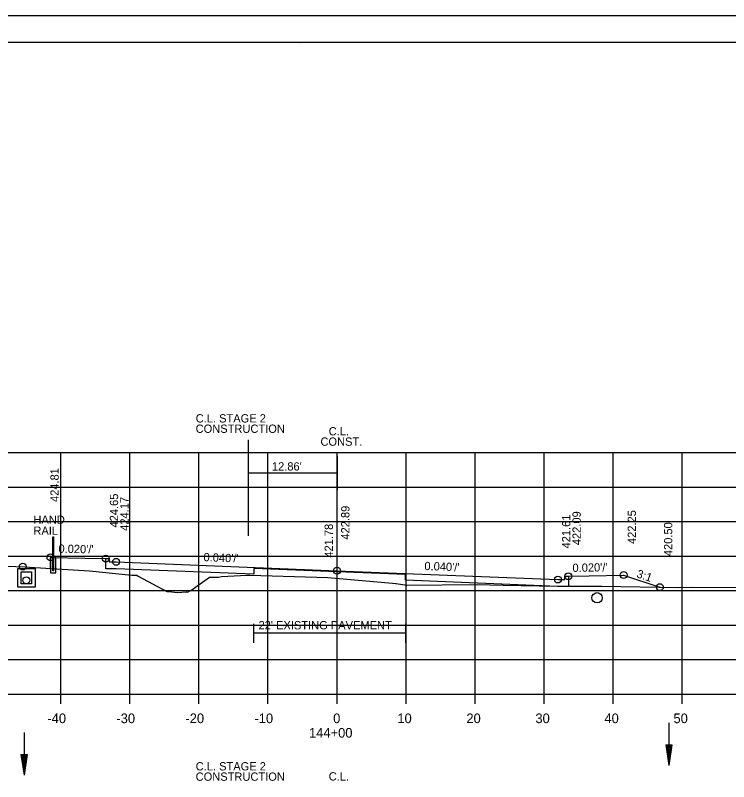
# Model space of a CAD drawing. Extents: x 1538688 to 1540766, y 656250 to 671912.
# Drawn here: x 1538811.6 to 1538914.9, y 663053.7 to 663164.7 of the extents above; entities that cross this region are included whole.
import ezdxf

# ---------------------------------------------------------------- set-up
doc = ezdxf.new("R2010")
doc.units = 0
for name, color, linetype in [('15', 7, 'Continuous'), ('18', 7, 'Continuous'), ('20', 7, 'Continuous'), ('22', 7, 'Continuous'), ('26', 7, 'Continuous'), ('39', 7, 'Continuous'), ('41', 7, 'Continuous'), ('42', 7, 'Continuous'), ('7', 7, 'Continuous'), ('Borings', 7, 'Continuous'), ('Default', 7, 'Continuous'), ('Horizontal Alignment', 7, 'Continuous'), ('RipRap', 7, 'Continuous'), ('Wall Heights', 7, 'Continuous')]:
    doc.layers.add(name, color=color, linetype=linetype)

msp = doc.modelspace()

# ---------------------------------------------------------------- linework, layer by layer
at = {"layer": '15'}
for p, q in [((1538905.79, 663059.03), (1538906.24, 663056.03)), ((1538905.79, 663059.03), (1538906.69, 663059.03)), ((1538905.87, 663059.03), (1538906.24, 663056.53)), ((1538905.95, 663059.03), (1538906.24, 663057.05)), ((1538906.02, 663059.03), (1538906.24, 663057.55)), ((1538906.1, 663059.03), (1538906.24, 663058.06)), ((1538906.17, 663059.03), (1538906.24, 663058.56)), ((1538906.69, 663059.03), (1538906.24, 663056.03)), ((1538906.39, 663059.03), (1538906.24, 663058.06)), ((1538906.54, 663059.03), (1538906.24, 663057.05)), ((1538906.62, 663059.03), (1538906.24, 663056.53)), ((1538906.47, 663059.03), (1538906.24, 663057.55)), ((1538906.31, 663059.03), (1538906.24, 663058.56)), ((1538812.39, 663057.6), (1538812.84, 663054.6)), ((1538812.39, 663057.6), (1538813.29, 663057.6)), ((1538812.47, 663057.6), (1538812.84, 663055.1)), ((1538812.54, 663057.6), (1538812.84, 663055.62)), ((1538812.62, 663057.6), (1538812.84, 663056.12)), ((1538812.7, 663057.6), (1538812.84, 663056.63)), ((1538812.77, 663057.6), (1538812.84, 663057.13)), ((1538813.29, 663057.6), (1538812.84, 663054.6)), ((1538812.99, 663057.6), (1538812.84, 663056.63)), ((1538813.14, 663057.6), (1538812.84, 663055.62)), ((1538813.22, 663057.6), (1538812.84, 663055.1)), ((1538813.06, 663057.6), (1538812.84, 663056.12)), ((1538812.91, 663057.6), (1538812.84, 663057.13))]:
    msp.add_line(p, q, dxfattribs=at)
at = {"layer": '18'}
msp.add_lwpolyline([(1538800.87, 663085.26), (1538813.02, 663084.82), (1538813.65, 663084.78), (1538822.3, 663084.24), (1538828.47, 663083.62), (1538829.18, 663083.58), (1538829.37, 663083.45), (1538833.55, 663081.21), (1538833.81, 663081.22), (1538835.09, 663081.07), (1538836.39, 663081.18), (1538836.52, 663081.15), (1538837.01, 663081.4), (1538839.7, 663083.31), (1538841, 663083.33), (1538841.44, 663083.4), (1538845.13, 663083.62), (1538845.36, 663083.62), (1538845.54, 663083.61), (1538856.87, 663083.25), (1538866.2, 663082.42), (1538866.65, 663082.38), (1538866.75, 663082.38), (1538868.3, 663082.17), (1538878.48, 663082.24), (1538882.26, 663082.13), (1538890.1, 663082.03), (1538896.52, 663082.02), (1538907.59, 663081.81), (1538909.58, 663081.85), (1538916.48, 663081.83)], dxfattribs=at)
at = {"layer": '20'}
msp.add_lwpolyline([(1538816.67, 663084.59), (1538816.67, 663086.17), (1538821.67, 663086.07), (1538824.67, 663086.01), (1538825.17, 663086.01), (1538825.18, 663085.51), (1538826.18, 663085.53), (1538858.18, 663084.25), (1538890.18, 663082.97), (1538891.18, 663082.95), (1538891.19, 663083.45), (1538891.69, 663083.45), (1538894.69, 663083.51), (1538899.69, 663083.61), (1538904.95, 663081.86)], dxfattribs=at)
at = {"layer": '22'}
for p, q in [((1538718.18, 663101.36), (1538998.18, 663101.36)), ((1538818.18, 663066.36), (1538818.18, 663101.36)), ((1538828.18, 663066.36), (1538828.18, 663101.36)), ((1538838.18, 663066.36), (1538838.18, 663101.36)), ((1538848.18, 663066.36), (1538848.18, 663101.36)), ((1538858.18, 663066.36), (1538858.18, 663101.36)), ((1538868.18, 663066.36), (1538868.18, 663101.36)), ((1538878.18, 663066.36), (1538878.18, 663101.36)), ((1538888.18, 663066.36), (1538888.18, 663101.36)), ((1538898.18, 663066.36), (1538898.18, 663101.36)), ((1538908.18, 663066.36), (1538908.18, 663101.36)), ((1538718.18, 663096.36), (1538998.18, 663096.36)), ((1538718.18, 663091.36), (1538998.18, 663091.36)), ((1538718.18, 663086.36), (1538998.18, 663086.36)), ((1538718.18, 663081.36), (1538998.18, 663081.36)), ((1538718.18, 663076.36), (1538998.18, 663076.36)), ((1538718.18, 663071.36), (1538998.18, 663071.36)), ((1538718.18, 663066.36), (1538998.18, 663066.36))]:
    msp.add_line(p, q, dxfattribs=at)
at = {"layer": '26'}
msp.add_line((1538687.78, 663164.71), (1539021.11, 663164.71), dxfattribs=at)
msp.add_lwpolyline([(1538687.77, 663164.71), (1539021.11, 663164.71), (1539021.11, 662951.38), (1538687.77, 662951.38)], close=True, dxfattribs=at)
for centre in [(1538816.67, 663086.17), (1538824.67, 663086.01), (1538812.66, 663084.84), (1538826.18, 663085.53), (1538858.18, 663084.25), (1538890.18, 663082.97), (1538891.69, 663083.45), (1538899.69, 663083.61), (1538904.95, 663081.86)]:
    msp.add_circle(centre, 0.5, dxfattribs=at)
at = {"layer": '39'}
for p, q in [((1538906.24, 663062.22), (1538906.24, 663056.03)), ((1538812.84, 663060.79), (1538812.84, 663054.6))]:
    msp.add_line(p, q, dxfattribs=at)
for points in [[(1538813.18, 663084.56), (1538814.43, 663084.56), (1538814.43, 663081.86), (1538813.18, 663081.86), (1538811.93, 663081.86), (1538811.93, 663084.56)], [(1538813.18, 663084.06), (1538813.93, 663084.06), (1538813.93, 663082.36), (1538813.18, 663082.36), (1538812.43, 663082.36), (1538812.43, 663084.06)]]:
    msp.add_lwpolyline(points, close=True, dxfattribs=at)
for centre, radius in [((1538813.18, 663082.86), 0.5), ((1538895.85, 663080.32), 0.75)]:
    msp.add_circle(centre, radius, dxfattribs=at)
at = {"layer": '41'}
for points in [[(1538817.13, 663089.17), (1538817.13, 663084.25), (1538817, 663084.25), (1538817, 663089.17), (1538817.13, 663089.17)], [(1538817, 663086.17), (1538816.67, 663086.17), (1538816.67, 663083.92), (1538817.46, 663083.92), (1538817.46, 663086.17), (1538817.13, 663086.17)]]:
    msp.add_lwpolyline(points, dxfattribs=at)
at = {"layer": '7'}
for p, q in [((1538846.1, 663076.56), (1538846.1, 663073.81)), ((1538868.1, 663076.56), (1538868.1, 663073.81)), ((1538868.1, 663075.19), (1538846.1, 663075.19))]:
    msp.add_line(p, q, dxfattribs=at)
at = {"layer": 'Borings'}
for p, q in [((1538718.18, 663066.36), (1538998.18, 663066.36)), ((1538818.18, 663064.96), (1538818.18, 663066.36)), ((1538828.18, 663064.96), (1538828.18, 663066.36)), ((1538838.18, 663064.96), (1538838.18, 663066.36)), ((1538848.18, 663064.96), (1538848.18, 663066.36)), ((1538858.18, 663064.96), (1538858.18, 663066.36)), ((1538868.18, 663064.96), (1538868.18, 663066.36)), ((1538878.18, 663064.96), (1538878.18, 663066.36)), ((1538888.18, 663064.96), (1538888.18, 663066.36)), ((1538898.18, 663064.96), (1538898.18, 663066.36)), ((1538908.18, 663064.96), (1538908.18, 663066.36))]:
    msp.add_line(p, q, dxfattribs=at)
at = {"layer": 'Default'}
for p, q in [((1538845.32, 663103.2), (1538845.32, 663089.29)), ((1538858.18, 663100.9), (1538858.18, 663095.9)), ((1538858.18, 663098.4), (1538845.32, 663098.4))]:
    msp.add_line(p, q, dxfattribs=at)
at = {"layer": 'RipRap'}
for p, q in [((1538700.18, 663160.82), (1539016.36, 663160.82)), ((1538852.7, 663160.56), (1538852.7, 663160.56)), ((1538852.7, 663160.56), (1538852.7, 663160.56))]:
    msp.add_line(p, q, dxfattribs=at)
at = {"layer": 'Wall Heights'}
msp.add_lwpolyline([(1538891.69, 663083.45), (1538891.69, 663081.95), (1538890.18, 663081.97), (1538868.11, 663082.86), (1538868.11, 663083.69), (1538858.18, 663084.09), (1538846.11, 663084.57), (1538846.11, 663083.74), (1538826.18, 663084.53), (1538824.67, 663084.51), (1538824.67, 663086.01)], dxfattribs=at)

# ---------------------------------------------------------------- texts
at = {"layer": '41'}
for s, p in [('424.81', (1538817.86, 663094.2)), ('424.65', (1538826.47, 663090.51)), ('424.17', (1538827.98, 663090.03)), ('422.89', (1538859.98, 663088.75)), ('421.61', (1538891.98, 663087.47)), ('422.09', (1538893.49, 663087.95)), ('422.25', (1538901.49, 663088.11)), ('421.78', (1538857.58, 663086.14)), ('420.50', (1538906.75, 663086.36))]:
    msp.add_text(s, height=1.2, rotation=90, dxfattribs=at).set_placement(p)
for s, p in [('HAND', (1538814.2, 663091.04)), ('RAIL', (1538814.2, 663089.45))]:
    msp.add_text(s, height=1.2, dxfattribs=at).set_placement(p)
at = {"layer": '42'}
for s, rotation, p in [("0.020'/'", 358.8542, (1538817.82, 663086.85)), ("0.040'/'", 357.7094, (1538838.82, 663085.63)), ("0.040'/'", 357.7094, (1538870.82, 663084.35)), ("0.020'/'", 1.1458, (1538892.3, 663084.06)), ('3:1', 341.5651, (1538901.48, 663083.31))]:
    msp.add_text(s, height=1.2, rotation=rotation, dxfattribs=at).set_placement(p)
at = {"layer": '7'}
msp.add_text("22' EXISTING PAVEMENT", height=1.2, dxfattribs=at).set_placement((1538846.81, 663075.75))
at = {"layer": 'Default'}
for s, p in [('C.L. STAGE 2', (1538837.71, 663105.72)), ('CONSTRUCTION', (1538837.7, 663104.22)), ('C.L.', (1538856.98, 663103.85)), ('CONST.', (1538855.78, 663102.35)), ("12.86'", (1538848.75, 663098.76)), ('C.L. STAGE 2', (1538837.71, 663055.31)), ('CONSTRUCTION', (1538837.7, 663053.81)), ('C.L.', (1538856.98, 663053.85))]:
    msp.add_text(s, height=1.2, dxfattribs=at).set_placement(p)
at = {"layer": 'Horizontal Alignment'}
for s, p in [('-40', (1538816.22, 663062.16)), ('-30', (1538826.22, 663062.16)), ('-20', (1538836.22, 663062.16)), ('-10', (1538846.22, 663062.16)), ('0', (1538857.62, 663062.16)), ('10', (1538866.92, 663062.16)), ('20', (1538876.92, 663062.16)), ('30', (1538886.92, 663062.16)), ('40', (1538896.92, 663062.16)), ('50', (1538906.92, 663062.16)), ('144+00', (1538854.12, 663060.06))]:
    msp.add_text(s, height=1.4, dxfattribs=at).set_placement(p)

doc.saveas('drawing.dxf')
